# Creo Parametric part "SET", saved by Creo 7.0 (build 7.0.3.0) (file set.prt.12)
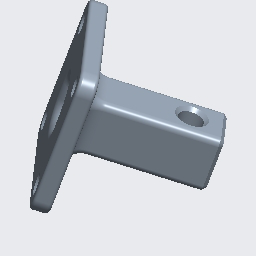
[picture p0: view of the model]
Units: millimeter Kilogram Sec (mmKs); MM, KILOGRAM, SECS

Created from: XX_SOLID_PART_MMKS_ABS.PRT

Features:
  1. coordinate system
  2. datum plane "RIGHT"
  3. datum plane "TOP"
  4. datum plane "FRONT"
  5. extrusion "Extrude 1"
  6. extruded cut "Extrude 2"
  7. extrusion "Extrude 3"
  8. round "Round 1"
  9. round "Round 2"
  10. round "Round 3"
  11. chamfer "Chamfer 1"
  12. extruded cut "Extrude 4"
  13. round "Round 4"
  14. chamfer "Chamfer 2"
  15. chamfer "Chamfer 3"
  16. extruded cut "Extrude 5"
  17. round "Round 5"
  18. round "Round 6"
  19. round "Round 7"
